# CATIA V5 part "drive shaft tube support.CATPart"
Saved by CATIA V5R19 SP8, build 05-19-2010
Part number: drive shaft tube support
Bounding box of the stored display mesh (mm): x -4.5 to 4.5, y 153.1 to 543.1, z -4.5 to 4.5
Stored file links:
  G:\EU_thinkMotion\CFAO_2010\MMS_groupe1\MMS_groupe1\A reprendre\gduval\CFAO kinematic ok\drive shaft tube support.CATPart
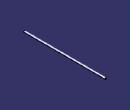
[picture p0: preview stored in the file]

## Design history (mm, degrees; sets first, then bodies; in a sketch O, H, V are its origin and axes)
Body1 (main body)
  Plane1: stored without definition
  Point1: stored without definition
  Line1: type PtDir, RefPoint Point1, Direction Plane1, Start 0, End 400
  Plane2: type Offset, RefPlane Plane1, Offset 390
  Sketch1 on Plane1, origin (0, 153.1, 0), H (-1, 0, 0), V (0, 0, 1)
    circle A1 centre (0, 0) radius 4.5
    point P1 (0, 0)
    reference projected point E1 (0, 0) from Point1
    circle A2 centre (0, 0) radius 2.25
    radius A1 = 4.5
    radius A2 = 2.25
    coincidence: P1 E1
    concentricity: A2 A1
  Pad1: profile Sketch1, direction (0, 1, 0), up to Plane2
